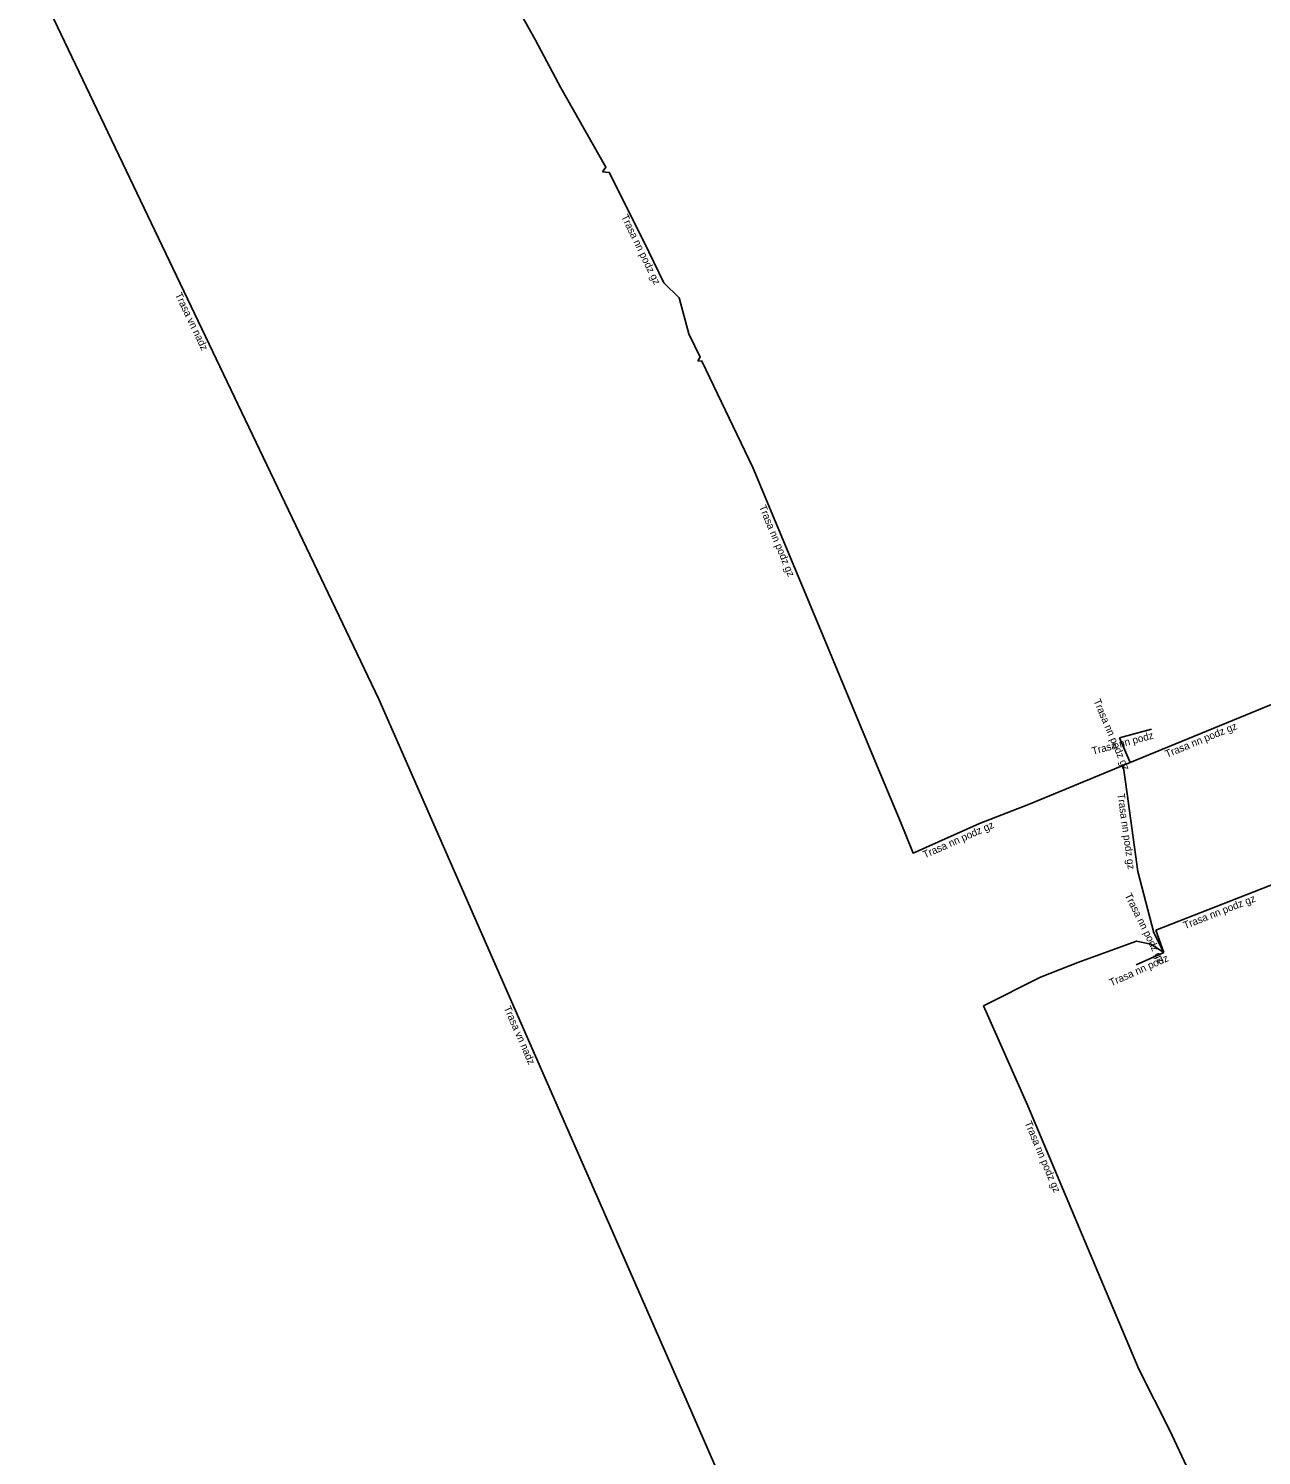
# Model space of a CAD drawing. Extents: x -467803 to -467116, y -1117596 to -1116713.
# Drawn here: x -467389 to -467305.8, y -1117152.7 to -1117056.5 of the extents above; entities that cross this region are included whole.
import ezdxf

# ---------------------------------------------------------------- set-up
doc = ezdxf.new("R2010")
doc.units = 0
for name, color, linetype in [('Popiskový text - Ostatní atributy Trasy', 7, 'Continuous'), ('Spojnice NN', 7, 'Continuous'), ('Spojnice VN', 7, 'Continuous')]:
    doc.layers.add(name, color=color, linetype=linetype)

msp = doc.modelspace()

# ---------------------------------------------------------------- linework, layer by layer
at = {"layer": 'Spojnice NN'}
for points in [[(-467355.53, -1117029.83), (-467355.458, -1117030.718), (-467360.07, -1117033.551), (-467356.85, -1117039.455), (-467362.6, -1117043.22), (-467354.77, -1117057.25), (-467353.07, -1117060.47), (-467350.025, -1117065.824), (-467350.26, -1117066.14)], [(-467350.26, -1117066.14), (-467349.793, -1117066.171), (-467347.47, -1117070.83), (-467346.12, -1117073.62), (-467345.08, -1117074.63), (-467344.43, -1117077.06), (-467343.665, -1117078.637), (-467343.83, -1117078.87)], [(-467343.83, -1117078.87), (-467343.542, -1117078.9), (-467340.11, -1117086.07), (-467335.41, -1117097.34), (-467331.965, -1117105.67)], [(-467314.67, -1117105.96), (-467303, -1117101.19)], [(-467315.382, -1117104.297), (-467313.233, -1117103.724)], [(-467314.67, -1117105.96), (-467315.382, -1117104.297)], [(-467331.965, -1117105.67), (-467330.16, -1117109.96), (-467329.77, -1117110.92), (-467329.31, -1117112.08), (-467324.82, -1117110.09), (-467321.53, -1117108.79), (-467314.67, -1117105.96)], [(-467315.145, -1117106.156), (-467314.88, -1117108.078), (-467314.146, -1117113.315), (-467313.069, -1117117.451)], [(-467300.76, -1117112.5), (-467312.93, -1117117.28), (-467312.407, -1117118.787)], [(-467313.069, -1117117.451), (-467312.407, -1117118.787)], [(-467312.407, -1117118.787), (-467313.277, -1117118.228), (-467314.244, -1117118.025), (-467318.21, -1117119.46), (-467320.72, -1117120.44), (-467324.56, -1117122.38), (-467321.57, -1117129.13), (-467316.48, -1117141.23), (-467314.08, -1117146.88), (-467311.99, -1117151.02), (-467309.426, -1117156.505), (-467309.59, -1117156.83)], [(-467312.407, -1117118.787), (-467314.257, -1117119.61)]]:
    msp.add_lwpolyline(points, dxfattribs=at)
at = {"layer": 'Spojnice VN'}
for points in [[(-467365.34, -1117101.699), (-467388.95, -1117052.25)], [(-467365.34, -1117101.699), (-467344.775, -1117148.57)], [(-467344.775, -1117148.57), (-467324.35, -1117195.35)]]:
    msp.add_lwpolyline(points, dxfattribs=at)

# ---------------------------------------------------------------- texts
at = {"layer": 'Popiskový text - Ostatní atributy Trasy'}
for s, rotation, p in [('Trasa nn podz gz', 295.82099, (-467349.004, -1117069.151)), ('Trasa vn nadz', 295.52275, (-467379.088, -1117074.414)), ('Trasa nn podz gz', 292.63791, (-467339.709, -1117088.72)), ('Trasa nn podz gz', 293.17157, (-467317.156, -1117101.805)), ('Trasa nn podz gz', 22.23182, (-467312.194, -1117105.65)), ('Trasa nn podz', 14.91731, (-467317.182, -1117105.449)), ('Trasa nn podz gz', 277.97455, (-467315.535, -1117108.087)), ('Trasa nn podz gz', 23.90326, (-467328.523, -1117112.442)), ('Trasa nn podz gz', 296.39217, (-467315.051, -1117114.92)), ('Trasa nn podz gz', 21.44337, (-467310.974, -1117117.21)), ('Trasa nn podz', 23.97272, (-467315.944, -1117121.071)), ('Trasa vn nadz', 293.68973, (-467356.918, -1117122.513)), ('Trasa nn podz gz', 292.8146, (-467321.798, -1117130.265))]:
    msp.add_text(s, height=0.5, rotation=rotation, dxfattribs=at).set_placement(p)

doc.saveas('drawing.dxf')
